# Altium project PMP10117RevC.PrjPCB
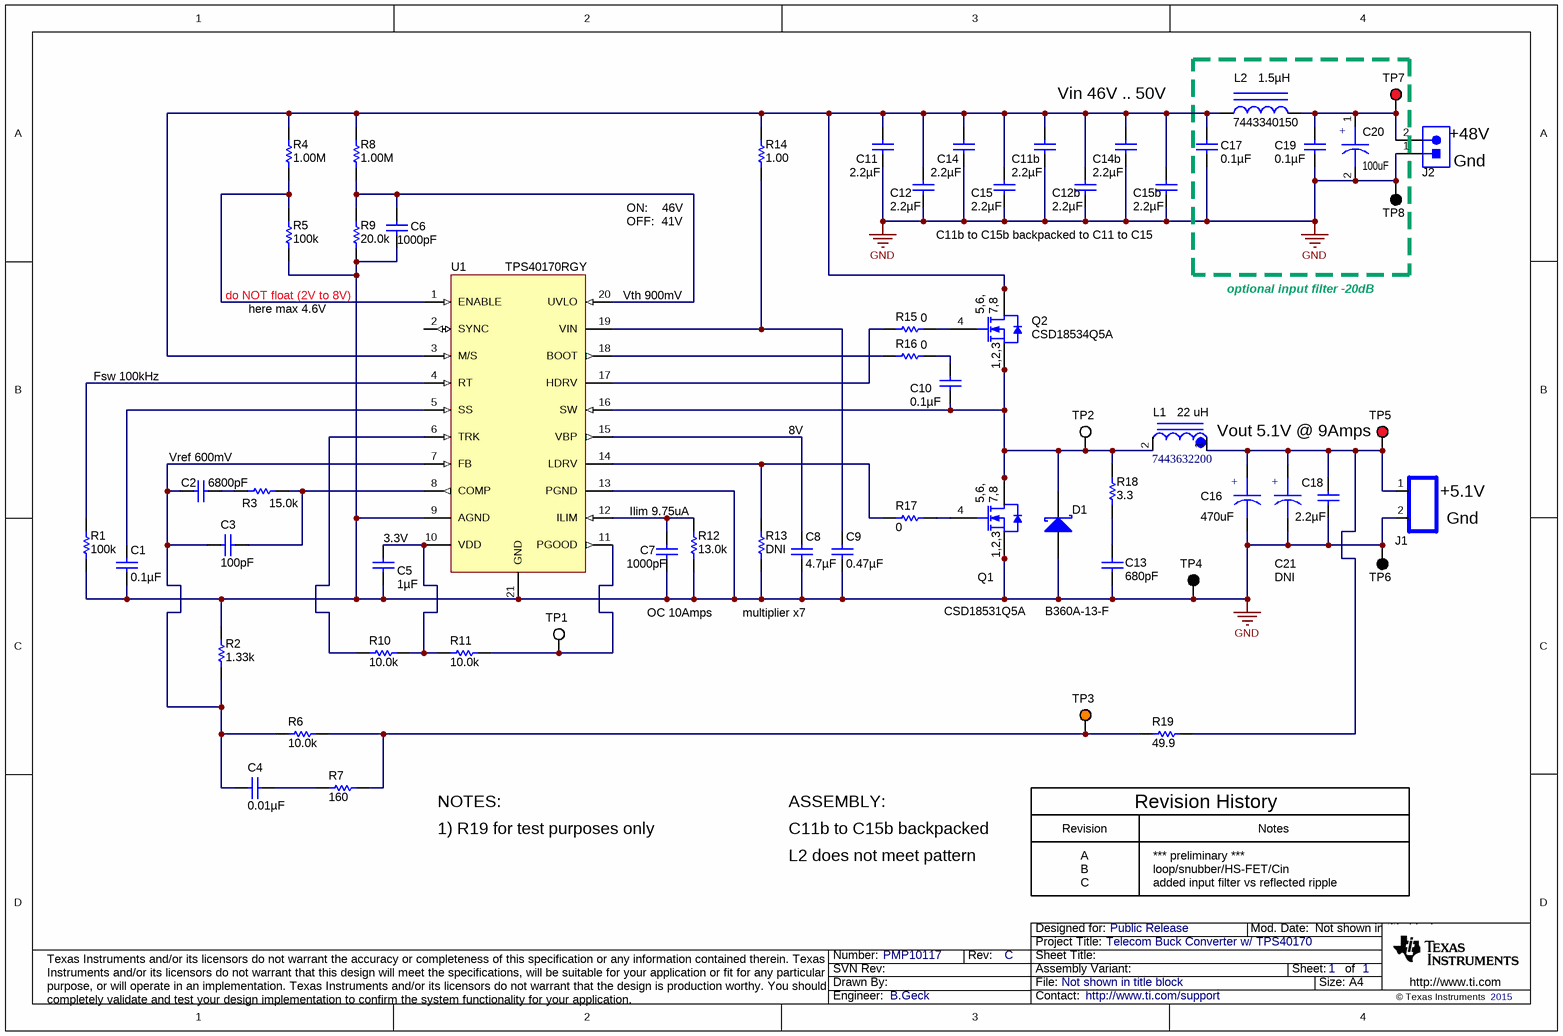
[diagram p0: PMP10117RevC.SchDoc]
CopyrightYear: 2015; PCB_Layout: B.Geck; PCB_Rev: C; PRJ_Customer: Public Release; PRJ_Engineer: B.Geck; PRJ_Number: PMP10117; PRJ_Title: Telecom Buck Converter w/ TPS40170; SCH_Rev: C; TechSupport: http://www.ti.com/support
1 sheet, 60 parts. Net scope: global (net labels, ports and power ports of the same name join across sheets).
Board file: PMP10117RevC.PcbDoc

## Sheet PMP10117RevC.SchDoc
size A4; Date: Not shown in title block; ApprovedBy: Not shown in title block; CheckedBy: Not shown in title block; Author: Not shown in title block; CompanyName: Not shown in title block; Engineer: Not shown in title block; Organization: Not shown in title block; Address1: Not shown in title block; Address2: Not shown in title block; Address3: Not shown in title block; Address4: Not shown in title block; DocumentNumber: 1; Revision: Use project parameter SCH_Rev; SheetNumber: 1; SheetTotal: 1; PageSetup: Record=PageOptions|CenterHorizontal=True|CenterVertical=True|PrintScale=0.97|XCorrection=1.00|YCorrection=1.00|PrintKind=0|BorderSize=5000000|LeftOffset=0|BottomOffset=0|Orientation=2|PaperLength=1000|PaperWidth=1000|Scale=100|PaperSource=15|PrintQuality=600|MediaType=1|DitherType=10|PaperKind=A4|PrintScaleMode=1

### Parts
C1  ValueDisplayed: 0.1µF  [0402]  (hidden comment: GRM155R71C104KA88D)
C2  ValueDisplayed: 6800pF  [0402]  (hidden comment: GRM155R71E682KA01D)
C3  ValueDisplayed: 100pF  [0402]  (hidden comment: GRM1535C1H101JDD5D)
C4  ValueDisplayed: 0.01µF  [0402]  (hidden comment: GRM155R71C103KA01D)
C5  ValueDisplayed: 1µF  [0603]  (hidden comment: GRM188R71C105KA12D)
C6  ValueDisplayed: 1000pF  [0402]  (hidden comment: GRM155R71C102KA01D)
C7  ValueDisplayed: 1000pF  [0402]  (hidden comment: GRM155R71C102KA01D)
C8  ValueDisplayed: 4.7µF  [0805_HV]  (hidden comment: GRM21BR71C475KA73L)
C9  ValueDisplayed: 0.47µF  [0805_HV]  (hidden comment: GRM21BR72A474KA73L)
C10  ValueDisplayed: 0.1µF  [0603]  (hidden comment: GRM188R72A104KA35D)
C11  ValueDisplayed: 2.2µF  [1210]  (hidden comment: GRM32ER72A225KA35L)
C11b  ValueDisplayed: 2.2µF  [1210]  (hidden comment: GRM32ER72A225KA35L)
C12  ValueDisplayed: 2.2µF  [1210]  (hidden comment: GRM32ER72A225KA35L)
C12b  ValueDisplayed: 2.2µF  [1210]  (hidden comment: GRM32ER72A225KA35L)
C13  ValueDisplayed: 680pF  [0603]  (hidden comment: GRM188R72A681KA01D)
C14  ValueDisplayed: 2.2µF  [1210]  (hidden comment: GRM32ER72A225KA35L)
C14b  ValueDisplayed: 2.2µF  [1210]  (hidden comment: GRM32ER72A225KA35L)
C15  ValueDisplayed: 2.2µF  [1210]  (hidden comment: GRM32ER72A225KA35L)
C15b  ValueDisplayed: 2.2µF  [1210]  (hidden comment: GRM32ER72A225KA35L)
C16  value 470uF  [CAPSMT_6_D3L]  (hidden comment: 6TPF470MAH)
C17  ValueDisplayed: 0.1µF  [0603]  (hidden comment: GRM188R72A104KA35D)
C18  ValueDisplayed: 2.2µF  [0603]  (hidden comment: GRM188R71A225KE15D)
C19  ValueDisplayed: 0.1µF  [0603]  (hidden comment: GRM188R72A104KA35D)
C20  value 100uF  [CAP_EEVFK_SIZE_G]  (hidden comment: EEEFK1J101P)
C21  value DNI  [CAPSMT_6_D3L]  (hidden comment: 6TPF470MAH)
D1  B360A-13-F  [SMA]
J1  TBLK_15A_2X5.1MM  [TB_2X5.1MM]  (value not drawn)
J2  ED555/2DS  [TERM_BLK_ED555-2DS]  (value not drawn)
L1  value 22 uH  [IND_WE21.5X21.8MM-3P]  (hidden comment: 7443632200)
L2  7443340150  ValueDisplayed: 1.5µH  [WE-HCC-8X7]
Q1  CSD18531Q5A  [TRANS_NexFET_Q5A]
Q2  CSD18534Q5A  [TRANS_NexFET_Q5A]
R1  ValueDisplayed: 100k  [0402]  (hidden comment: CRCW0402100KFKED)
R2  ValueDisplayed: 1.33k  [0402]  (hidden comment: CRCW04021K33FKED)
R3  ValueDisplayed: 15.0k  [0402]  (hidden comment: CRCW040215K0FKED)
R4  ValueDisplayed: 1.00M  [0603]  (hidden comment: CRCW06031M00FKEA)
R5  ValueDisplayed: 100k  [0402]  (hidden comment: CRCW0402100KFKED)
R6  ValueDisplayed: 10.0k  [0402]  (hidden comment: CRCW040210K0FKED)
R7  ValueDisplayed: 160  [0402]  (hidden comment: CRCW0402160RJNED)
R8  ValueDisplayed: 1.00M  [0603]  (hidden comment: CRCW06031M00FKEA)
R9  ValueDisplayed: 20.0k  [0402]  (hidden comment: CRCW040220K0FKED)
R10  ValueDisplayed: 10.0k  [0402]  (hidden comment: CRCW040210K0FKED)
R11  ValueDisplayed: 10.0k  [0402]  (hidden comment: CRCW040210K0FKED)
R12  ValueDisplayed: 13.0k  [0402]  (hidden comment: CRCW040213K0FKED)
R13  ValueDisplayed: DNI  [0402]  (hidden comment: CRCW040210K0FKED)
R14  ValueDisplayed: 1.00  [0603]  (hidden comment: CRCW06031R00FKEA)
R15  ValueDisplayed: 0  [0402]  (hidden comment: CRCW04020000Z0ED)
R16  ValueDisplayed: 0  [0402]  (hidden comment: CRCW04020000Z0ED)
R17  ValueDisplayed: 0  [0402]  (hidden comment: CRCW04020000Z0ED)
R18  ValueDisplayed: 3.3  [1210M]  (hidden comment: ERJ-P14J3R3U)
R19  ValueDisplayed: 49.9  [0402]  (hidden comment: CRCW040249R9FKED)
TP1  5002  [Keystone5002]  (value not drawn)
TP2  5002  [Keystone5002]  (value not drawn)
TP3  5003  [Keystone5003]  (value not drawn)
TP4  5001  [Keystone5001]  (value not drawn)
TP5  5000  [Keystone5000]  (value not drawn)
TP6  5001  [Keystone5001]  (value not drawn)
TP7  5000  [Keystone5000]  (value not drawn)
TP8  5001  [Keystone5001]  (value not drawn)
U1  TPS40170RGY  [RGY0020A]

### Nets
GND: C1.2 C5.2 C6.2 C7.2 C8.2 C9.2 C11.2 C11b.2 C12.2 C12b.2 C13.2 C14.2 C14b.2 C15.2 C15b.2 C16.2 C17.2 C18.2 C19.2 C20.2 C21.2 D1.2(A) J1.2 J2.1 Q1.1(S) Q1.2(S) Q1.3(S) R1.1 R2.2 R5.1 R9.1 R12.1 R13.1 TP4.1 TP6.1 TP8.1 U1.9(AGND) U1.13(PGND) U1.21(GND)
NetC1_1: C1.1 U1.5(SS)
NetC2_1: C2.1 R3.1
NetC2_2: C2.2 C3.2 C4.2 R2.1 R6.2 U1.7(FB)
NetC3_1: C3.1 R3.2 U1.8(COMP)
NetC4_1: C4.1 R7.1
NetC5_1: C5.1 R10.1 R11.2 U1.10(VDD)
NetC6_1: C6.1 R8.1 R9.2 U1.20(UVLO)
NetC7_1: C7.1 R12.2 U1.12(ILIM)
NetC8_1: C8.1 U1.15(VBP)
NetC9_1: C9.1 R14.1 U1.19(VIN)
NetC10_1: C10.1 R16.2
NetC10_2: C10.2 D1.1(K) L1.2 Q1.5(D) Q1.6(D) Q1.7(D) Q1.8(D) Q1.9(D) Q2.1(S) Q2.2(S) Q2.3(S) R18.2 TP2.1 U1.16(SW)
NetC11_1: C11.1 C11b.1 C12.1 C12b.1 C14.1 C14b.1 C15.1 C15b.1 C17.1 L2.1 Q2.5(D) Q2.6(D) Q2.7(D) Q2.8(D) Q2.9(D) R4.2 R8.2 R14.2 U1.3(M/S)
NetC13_1: C13.1 R18.1
NetC16_1: C16.1 C18.1 C21.1 J1.1 L1.1 R19.2 TP5.1
NetC19_1: C19.1 C20.1 J2.2 L2.2 TP7.1
NetQ1_4: Q1.4(G) R17.2
NetQ2_4: Q2.4(G) R15.2
NetR1_2: R1.2 U1.4(RT)
NetR4_1: R4.1 R5.2 U1.1(ENABLE)
NetR6_1: R6.1 R7.2 R19.1 TP3.1
NetR10_2: R10.2 U1.6(TRK)
NetR11_1: R11.1 TP1.1 U1.11(PGOOD)
NetR13_2: R13.2 R17.1 U1.14(LDRV)
NetR15_1: R15.1 U1.17(HDRV)
NetR16_1: R16.1 U1.18(BOOT)

Not connected (* = marked no-connect by the designer): U1 2(SYNC)

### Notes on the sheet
- Vin 46V .. 50V
- (near J2) +48V
- (near J2) Gnd
- ON:    46V
- OFF:  41V
- C11b to C15b backpacked to C11 to C15
- here max 4.6V
- do NOT float (2V to 8V)
- (near U1) Vth 900mV
- optional input filter -20dB
- Fsw 100kHz
- 8V
- Vout 5.1V @ 9Amps
- Vref 600mV
- (near R12) Ilim 9.75uA
- (near J1) +5.1V
- (near J1) Gnd
- (near C5) 3.3V
- OC 10Amps
- multiplier x7
- NOTES:
- 1) R19 for test purposes only
- ASSEMBLY:
- C11b to C15b backpacked
- L2 does not meet pattern
- Revision
- A
- *** preliminary ***
- Revision History
- Notes
- B
- C
- added input filter vs reflected ripple
- loop/snubber/HS-FET/Cin

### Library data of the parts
C1 = GRM155R71C104KA88D: CAP, CERM, 0.1 µF, 16 V, +/- 10%, X7R, 0402; Manufacturer: MuRata; Polarized: N; CompType: Capacitor; Value: 0.1uF; U/M: EA; Cap_F: 0.0000001; Tolerance_%: 10; Value1: Unknown; VDC_V: 16; Value2: 16V; TaMin_C: -55; TaMax_C: 125
C2 = GRM155R71E682KA01D: CAP, CERM, 6800 pF, 25 V, +/- 10%, X7R, 0402; Manufacturer: MuRata; Polarized: N; CompType: Capacitor; Value: 6800pF; U/M: EA; Cap_F: 0.0000000068; Tolerance_%: 10; Value1: Unknown; VDC_V: 25; Value2: 25V; TaMin_C: -55; TaMax_C: 125
C3 = GRM1535C1H101JDD5D: CAP, CERM, 100 pF, 50 V, +/- 5%, C0G/NP0, 0402; Manufacturer: MuRata; Polarized: N; CompType: Capacitor; Value: 100pF; U/M: EA; Cap_F: 0.0000000001; Tolerance_%: 5; Value1: Unknown; VDC_V: 50; Value2: 50V; TaMin_C: -55; TaMax_C: 125
C4 = GRM155R71C103KA01D: CAP, CERM, 0.01 µF, 16 V, +/- 10%, X7R, 0402; Manufacturer: MuRata; Polarized: N; CompType: Capacitor; Value: 0.01uF; U/M: EA; Cap_F: 0.00000001; Tolerance_%: 10; Value1: Unknown; VDC_V: 16; Value2: 16V; TaMin_C: -55; TaMax_C: 125
C5 = GRM188R71C105KA12D: CAP, CERM, 1 µF, 16 V, +/- 10%, X7R, 0603; Manufacturer: MuRata; Polarized: N; CompType: Capacitor; Value: 1uF; U/M: EA; Cap_F: 0.000001; Tolerance_%: 10; ESR_ohm: 0.011; Value1: 0.011 ohm; VDC_V: 16; Value2: 16V; TaMin_C: -55; TaMax_C: 125
C6 C7 = GRM155R71C102KA01D: CAP, CERM, 1000 pF, 16 V, +/- 10%, X7R, 0402; Manufacturer: MuRata; Polarized: N; CompType: Capacitor; Value: 1000pF; U/M: EA; Cap_F: 0.000000001; Tolerance_%: 10; Value1: Unknown; VDC_V: 16; Value2: 16V; TaMin_C: -55; TaMax_C: 125
C8 = GRM21BR71C475KA73L: CAP, CERM, 4.7 µF, 16 V, +/- 10%, X7R, 0805; Manufacturer: MuRata; Polarized: N; CompType: Capacitor; Value: 4.7uF; U/M: EA; Cap_F: 0.0000047; Tolerance_%: 10; ESR_ohm: 0.006; Value1: 0.006 ohm; VDC_V: 16; Value2: 16V; TaMin_C: -55; TaMax_C: 125; Cap_Case: 0805
C9 = GRM21BR72A474KA73L: CAP, CERM, 0.47 µF, 100 V, +/- 10%, X7R, 0805; Manufacturer: MuRata; Polarized: N; CompType: Capacitor; Value: 0.47uF; U/M: EA; Cap_F: 0.00000047; Tolerance_%: 10; Value1: Unknown; VDC_V: 100; Value2: 100V; TaMin_C: -55; TaMax_C: 125; Cap_Case: 0805
C10 C17 C19 = GRM188R72A104KA35D: CAP, CERM, 0.1 µF, 100 V, +/- 10%, X7R, 0603; Manufacturer: MuRata; Polarized: N; CompType: Capacitor; Value: 0.1uF; U/M: EA; Cap_F: 0.0000001; Tolerance_%: 10; Value1: Unknown; VDC_V: 100; Value2: 100V; TaMin_C: -55; TaMax_C: 125
C11 C11b C12 C12b C14 C14b C15 C15b = GRM32ER72A225KA35L: CAP, CERM, 2.2 µF, 100 V, +/- 10%, X7R, 1210; Manufacturer: MuRata; Polarized: N; CompType: Capacitor; Value: 2.2uF; U/M: EA; Cap_F: 0.0000022; Tolerance_%: 10; ESR_ohm: 0.007; Value1: 0.007 ohm; VDC_V: 100; Value2: 100V; IRMS_A: 4.4; TaMin_C: -55; TaMax_C: 125
C13 = GRM188R72A681KA01D: CAP, CERM, 680 pF, 100 V, +/- 10%, X7R, 0603; Manufacturer: MuRata; Polarized: N; CompType: Capacitor; Value: 680pF; U/M: EA; Cap_F: 0.00000000068; Tolerance_%: 10; Value1: Unknown; VDC_V: 100; Value2: 100V; TaMin_C: -55; TaMax_C: 125
C16 C21 = CAP_OSCON_SM-D: Capacitor, POSCAP, 6.3V, 20%, 10milliOhms, 4.4Arms; Manufacturer: Sanyo; Area: 159250
C18 = GRM188R71A225KE15D: CAP, CERM, 2.2 µF, 10 V, +/- 10%, X7R, 0603; Manufacturer: MuRata; Polarized: N; CompType: Capacitor; Value: 2.2uF; U/M: EA; Cap_F: 0.0000022; Tolerance_%: 10; ESR_ohm: 0.009; Value1: 0.009 ohm; Value2: 10V; TaMin_C: -55; TaMax_C: 125
C20 = CAP_EEEFK1-CODE_G: Capacitor, Aluminum, 63V, 100uF ±20%, 10mm x 10.2mm; Manufacturer: Panasonic; Area: 213,64
D1 = B360A-13-F: Diode, Schottky, 60V, 3A, SMA; Manufacturer: Diodes Inc.; U/M: EA; Vf_V: 0.7; Value2: 0.7V; Io_A: 3; Vr_V: 60; TJmax_C: 125; RJC_CperW: 25
J1 = TBLK_15A_2X5.1MM: Terminal Block, 2-pin, 15-A, 5.1mm; Manufacturer: OST; PartNumber: ED120/2DS; area: 141600; Value: ED120/2DS
J2 = ED555/2DS: Terminal Block, 6A, 3.5mm Pitch, 2-Pos, TH; Manufacturer: On-Shore Technology; SymbolCreator: a0412235; CompType: Connector; U/M: EA
L1 = IND_7443634700: Inductor, Power Coke, 10.7mOhm, 12Adc; Manufacturer: WE; Area: 529 mm
L2 = 7443340150: Inductor, Shielded Drum Core, Ferrite, 1.5 µH, 16.5 A, 0.0044 ohm, SMD; Manufacturer: Wurth Elektronik eiSos; Value: 1.5uH; Ind_H: 1.5E-6; Imax_A: 16.5; Irms: 16.5A @ 50C rise; Isat: 18.5A @ 30% inductance drop; DCR_ohm: 0.0044; Value2: 16.5A
Q1 = CSD18531Q5A: MOSFET, N-CH, 60V, 19A, SON 5x6mm; Manufacturer: Texas Instruments; Alternate Manufacturer: None; U/M: EA; ChType: N; VdsMax_V: 60; Value1: 0.0044 ohm; Rdson45_Ohm: 0.0044; Value2: 18 nC; QgTyp_nC: 18; Vgs_V: 20; IdsMax_A: 19
Q2 = CSD18534Q5A: MOSFET, N-CH, 60 V, 50 A, SON 5x6mm; Manufacturer: Texas Instruments; Alternate Manufacturer: None; U/M: EA; ChType: N; Value: 60V; VdsMax_V: 60; Value1: 0.0098 ohm; Rdson45_ohm: 0.0098; Value2: 22 nC; QgTyp_nC: 22; Vgs_V: 2.3; IdsMax_A: 50
R1 R5 = CRCW0402100KFKED: RES, 100 k, 1%, 0.063 W, 0402; Manufacturer: Vishay-Dale; CompType: Resistor; Res_ohm: 100000; Value: 100k; Tolerance_%: 1; Power_W: 0.063; Value2: 0.063W; VDC_V: 50; TempCo: 100 ppm/C; EIA_Code: E96; U/M: EA
R2 = CRCW04021K33FKED: RES, 1.33 k, 1%, 0.063 W, 0402; Manufacturer: Vishay-Dale; CompType: Resistor; Res_ohm: 1330; Value: 1.33k; Value_Code: 1k33; Tolerance_%: 1; Power_W: 0.063; Value2: 0.063W; VDC_V: 50; TempCo: 100 ppm/C; EIA_Code: E96; U/M: EA
R3 = CRCW040215K0FKED: RES, 15.0 k, 1%, 0.063 W, 0402; Manufacturer: Vishay-Dale; CompType: Resistor; Value: 15.0k; Res_ohm: 15000; Value_Code: 15k0; Tolerance_%: 1; Power_W: 0.063; Value2: 0.063W; VDC_V: 50; TempCo: 100 ppm/C; EIA_Code: E96; U/M: EA
R4 R8 = CRCW06031M00FKEA: RES, 1.00 M, 1%, 0.1 W, 0603; Manufacturer: Vishay-Dale; CompType: Resistor; Value: 1.00Meg; Res_ohm: 1000000; Value_Code: 1M00; Tolerance_%: 1; Power_W: 0.1; Value2: 0.1W; VDC_V: 75; TempCo: 100 ppm/C; EIA_Code: E96; U/M: EA
R6 R10 R11 R13 = CRCW040210K0FKED: RES, 10.0 k, 1%, 0.063 W, 0402; Manufacturer: Vishay-Dale; CompType: Resistor; Res_ohm: 10000; Value: 10.0k; Value_Code: 10k0; Tolerance_%: 1; Power_W: 0.063; Value2: 0.063W; VDC_V: 50; TempCo: 100 ppm/C; EIA_Code: E96; U/M: EA
R7 = CRCW0402160RJNED: RES, 160, 5%, 0.063 W, 0402; Manufacturer: Vishay-Dale; CompType: Resistor; Value: 160; Value_Code: 160R; Tolerance_%: 5; Power_W: 0.063; Value2: 0.063W; VDC_V: 50; TempCo: 200 ppm/C; EIA_Code: E24; U/M: EA
R9 = CRCW040220K0FKED: RES, 20.0 k, 1%, 0.063 W, 0402; Manufacturer: Vishay-Dale; CompType: Resistor; Res_ohm: 20000; Value: 20.0k; Value_Code: 20k0; Tolerance_%: 1; Power_W: 0.063; Value2: 0.063W; VDC_V: 50; TempCo: 100 ppm/C; EIA_Code: E96; U/M: EA
R12 = CRCW040213K0FKED: RES, 13.0 k, 1%, 0.063 W, 0402; Manufacturer: Vishay-Dale; CompType: Resistor; Value: 13.0k; Res_ohm: 13000; Value_Code: 13k0; Tolerance_%: 1; Power_W: 0.063; Value2: 0.063W; VDC_V: 50; TempCo: 100 ppm/C; EIA_Code: E96; U/M: EA
R14 = CRCW06031R00FKEA: RES, 1.00, 1%, 0.1 W, 0603; Manufacturer: Vishay-Dale; CompType: Resistor; Value: 1.00; Res_ohm: 1; Value_Code: 1R00; Power_W: 0.1; Value2: 0.1W; VDC_V: 75; TempCo: 100 ppm/C; EIA_Code: E96; U/M: EA
R15-R17 = CRCW04020000Z0ED: RES, 0, 5%, 0.063 W, 0402; Manufacturer: Vishay-Dale; CompType: Resistor; Value: 0; Value_Code: 0000; Tolerance_%: 5; Power_W: 0.063; Value2: 0.063W; VDC_V: 50; TempCo: 200 ppm/C; EIA_Code: E24; U/M: EA
R18 = ERJ-P14J3R3U: RES, 3.3, 5%, 0.5 W, 1210; Manufacturer: Panasonic; CompType: Resistor; Value: 3.3; Value_Code: 3R30; Tolerance_%: 5; Power_W: 0.5; Value2: 0.5W; VDC_V: 200; TempCo: 600 ppm/C; EIA_Code: E24; U/M: EA
R19 = CRCW040249R9FKED: RES, 49.9, 1%, 0.063 W, 0402; Manufacturer: Vishay-Dale; CompType: Resistor; Value: 49.9; Value_Code: 49R9; Tolerance_%: 1; Power_W: 0.063; Value2: 0.063W; VDC_V: 50; TempCo: 100 ppm/C; EIA_Code: E96; U/M: EA
TP1 TP2 = 5002: Test Point, Miniature, White, TH; Manufacturer: Keystone; CompType: Test Point Loop; U/M: EA
TP3 = 5003: Test Point, Miniature, Orange, TH; Manufacturer: Keystone; CompType: Test Point Loop; U/M: EA
TP4 TP6 TP8 = 5001: Test Point, Miniature, Black, TH; Manufacturer: Keystone; CompType: Test Point Loop; U/M: EA
TP5 TP7 = 5000: Test Point, Miniature, Red, TH; Manufacturer: Keystone; CompType: Test Point Loop; U/M: EA
U1 = TPS40170RGY: 4.5-v to 60-v wide-input synchronous PWM buck controller, RGY0020A; Alternate Manufacturer: None; Manufacturer: Texas Instruments; SymbolCreator: a0412235/PADS; CompType: IC; U/M: EA

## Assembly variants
001: all parts fitted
